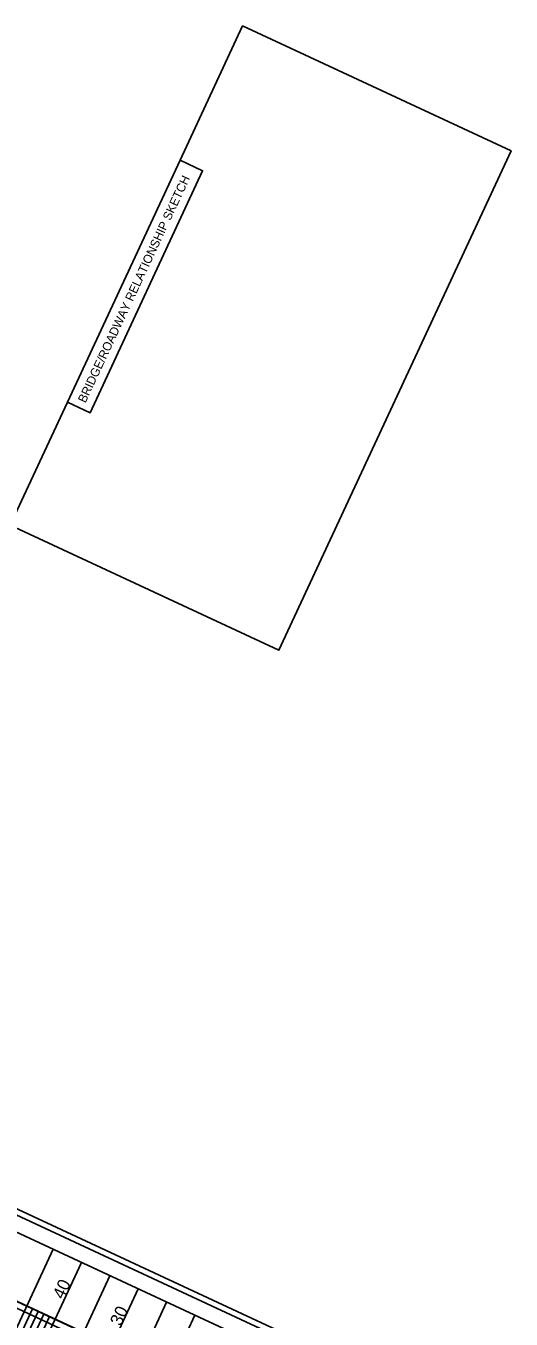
# Model space of a CAD drawing. Extents: x 2532214 to 2534758, y 714172 to 717266.
# Drawn here: x 2533573 to 2533961, y 716233 to 717266 of the extents above; entities that cross this region are included whole.
import ezdxf

# ---------------------------------------------------------------- set-up
doc = ezdxf.new("R2010")
doc.units = 0
for name, color, linetype in [('Auto Dimensioning', 7, 'Continuous'), ('Dimension Lines', 7, 'Continuous'), ('Mis Existing Structures', 7, 'Continuous'), ('Mis Ground Lines', 7, 'Continuous'), ('Plan Sheet', 7, 'Continuous'), ('Rebar Hooks Both Ends', 7, 'Continuous'), ('Rebar Lines', 7, 'Continuous'), ('Rebar with Hook On Right', 7, 'Continuous'), ('Structural Steel Channel 12', 7, 'Continuous'), ('Structural Steel Lines', 7, 'Continuous'), ('Sup Concrete Girder Lines', 7, 'Continuous')]:
    doc.layers.add(name, color=color, linetype=linetype)

msp = doc.modelspace()

# ---------------------------------------------------------------- linework, layer by layer
at = {"layer": 'Auto Dimensioning'}
for points in [[(2533560.6, 716867.3), (2533606.4, 716965.6), (2533624.4, 716957.2), (2533714.3, 717150.5), (2533696.3, 717158.9), (2533746.3, 717266.2), (2533960.9, 717166.3), (2533775.3, 716767.4)], [(2533606.4, 716965.6), (2533696.3, 717158.9), (2533714.3, 717150.5), (2533624.4, 716957.2)]]:
    msp.add_lwpolyline(points, close=True, dxfattribs=at)
at = {"layer": 'Dimension Lines'}
for p, q in [((2533594.9, 716288.9), (2532962.1, 714928.9)), ((2533007.4, 714907.8), (2533640.2, 716267.8)), ((2533685.5, 716246.7), (2533052.8, 714886.7))]:
    msp.add_line(p, q, dxfattribs=at)
at = {"layer": 'Mis Existing Structures'}
msp.add_lwpolyline([(2533194.3, 714651.5), (2533897.1, 716162.1), (2532940.5, 716607.1), (2532237.8, 715096.6)], close=True, dxfattribs=at)
at = {"layer": 'Mis Ground Lines'}
msp.add_lwpolyline([(2533206.9, 714631.3), (2533917.1, 716157.7), (2532924.3, 716619.6), (2532214.1, 715093.2)], close=True, dxfattribs=at)
at = {"layer": 'Plan Sheet'}
for p, q in [((2532984.8, 714918.3), (2533617.5, 716278.3)), ((2533030.1, 714897.2), (2533662.9, 716257.2)), ((2533075.4, 714876.1), (2533708.2, 716236.2))]:
    msp.add_line(p, q, dxfattribs=at)
at = {"layer": 'Rebar Lines'}
for p, q in [((2533413, 716312.8), (2533843.7, 716112.5)), ((2532987.7, 714972.1), (2533578.3, 716241.4)), ((2533582.8, 716239.3), (2532992.3, 714970)), ((2532996.8, 714967.9), (2533587.4, 716237.2)), ((2533591.9, 716235.1), (2533001.3, 714965.8))]:
    msp.add_line(p, q, dxfattribs=at)
at = {"layer": 'Structural Steel Channel 12'}
msp.add_lwpolyline([(2532824.5, 715048), (2533229.5, 715918.4), (2533415.1, 716317.4), (2533539.1, 716259.7), (2533845.8, 716117), (2533255.2, 714847.7)], close=True, dxfattribs=at)
at = {"layer": 'Structural Steel Lines'}
msp.add_lwpolyline([(2532937.5, 716594.7), (2532304.8, 715234.7), (2533256.8, 714791.8), (2533889.5, 716151.8)], close=True, dxfattribs=at)
at = {"layer": 'Sup Concrete Girder Lines'}
for p, q in [((2533845.8, 716117), (2533415.1, 716317.4)), ((2532984.8, 714918.3), (2533617.5, 716278.3)), ((2533662.9, 716257.2), (2533030.1, 714897.2)), ((2533075.4, 714876.1), (2533708.2, 716236.2))]:
    msp.add_line(p, q, dxfattribs=at)

# ---------------------------------------------------------------- texts
at = {"layer": 'Rebar Hooks Both Ends'}
for s, p in [('40', (2533603, 716248.4)), ('30', (2533648.9, 716227))]:
    msp.add_text(s, height=10, rotation=65.05, dxfattribs=at).set_placement(p)
at = {"layer": 'Rebar with Hook On Right'}
msp.add_text('BRIDGE/ROADWAY RELATIONSHIP SKETCH', height=7, rotation=65.05, dxfattribs=at).set_placement((2533620.7, 716964.5))

doc.saveas('drawing.dxf')
